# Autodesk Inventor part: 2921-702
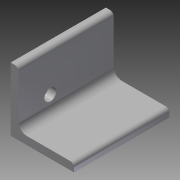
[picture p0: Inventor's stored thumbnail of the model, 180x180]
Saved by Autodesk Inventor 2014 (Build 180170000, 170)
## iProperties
Company: NHTSA/VRTC
Created: 2012-11
Part Number: 2921-702
Material: Steel, Mild
Document SubType Name: Modeling
Designer: Mike Vanvoorhis
Density: 7.86 g/cm^3
Project: CHILD SIDE IMPACT SLED
Description: LIGHT TRAP MOUNT ANGLE
Mass: 361.291 g
Surface Area: 163.343 cm^2
Volume: 45.9658 cm^3
Stock Number: L2"(50.8 mm) x 2"(50.8 mm) x 1/4"(6.4 mm) x 0'-3"(76.2 mm)
Appearance: Steel
Author: Dave Walker
Title: Light Trap Mount Angle
Subject: Child Side Impact Sled
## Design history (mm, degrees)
sketch "Sketch1"
  geometry: L1 (0, 0)-(0, 50.8); L2 (0, 50.8)-(-6.35, 50.8); L3 (0, 0)-(-50.8, 0); L4 (-50.8, 0)-(-50.8, 6.35); L5 (-50.8, 6.35)-(-12.7, 6.35); L6 (-6.35, 12.7)-(-6.35, 50.8); A1 r 6.35 centre (-12.7, 12.7) between (-12.7, 6.35) and (-6.35, 12.7); 1 further point
  constraints: 12 end point, 2 parallel, 2 perpendicular, 2 point on circle, 2 point on line, 2 tangent, 1 centre point, 1 vertical
  dimensions: "d0" = 50.8 distance of L1.start L1.end; "d1" = 6.35 distance of L1.end L2.end; "d2" = 50.8 distance of L1.start L3.end; "d3" = 6.35 distance of L3.end L4.end; "d4" = 44.45 distance of L4.end point (-6.35, 6.35); "d5" = 6.35 radius of A1
extrude "Extrusion1" new body sketch "Sketch1" distance "d6" = 76.2; taper "d7" = 0 deg
sketch "Sketch2"
  geometry: L1 (0, 0)-(0, 50.8) reference; L2 (0, 0)-(76.2, 0) reference; L3 (0, 50.8)-(76.2, 50.8) reference; L4 (0, 19.05)-(50.8, 19.05); L5 (50.8, 19.05)-(50.8, 0); 2 further points
  constraints: 4 end point, 2 coincident, 2 point on line, 1 parallel, 1 perpendicular
  dimensions: "d8" = 50.8 distance of L4.start L4.end; "d9" = 19.05 distance of L4.end L5.end
hole "Hole1" sketch "Sketch2" at (50.8, 19.05) diameter "d10" = 9.525; stored, may be unused: countersink angle "d14" = 82 deg, drill point angle "d16" = 118 deg; dims "d11" = 19.05, "d12" = 9.525, "d13" = 6.35, "d15" = 25.4
fillet "Fillet1" dims "d17" = 3.175
body "Solid1"
